(* Logix 5000 project; controller GracoPd2kDual_Example vendor 1 type 14 code 196 rev 32.11; software revision 32.04; part 3 of 4 *)

ADD_ON_INSTRUCTION GracoPd2kDual_SendDCS   (* revision 1.0 *)
// Help:
// Sends a dynamic command structure (DCS) to the PD2K system.
// For more information about DCS commands, see the system operation manual.
// State Codes:
// * 0000 (IDLE) - Idle
// * 1000 (BUSY) - Busy
// * 2000 (DONE) - Done
// * 4000 (ABORT) - Command overwritten by another process
// * 8000 (ERROR) - Invalid command ID
// * 8001 (ERROR) - Timeout waiting for DCS registers
// * 8002 (ERROR) - Command unsuccessful
VAR_IN_OUT
   io_moduleStatus : DINT[62]; {required}   // Data from device to PLC
   io_moduleCmds : DINT[30]; {required}   // Data from PLC to device
END_VAR
VAR_INPUT
   i_execute : BOOL; {visible}   // Execute command
   i_cmdID : DINT; {visible}   // Command ID number
   i_arg0 : DINT; {visible}   // Argument 0
   i_arg1 : DINT; {visible}   // Argument 1
   i_arg2 : DINT; {visible}   // Argument 2
   i_arg3 : DINT; {visible}   // Argument 3
   i_arg4 : DINT; {visible}   // Argument 4
   i_arg5 : DINT; {visible}   // Argument 5
   i_arg6 : DINT; {visible}   // Argument 6
   i_arg7 : DINT; {visible}   // Argument 7
   i_arg8 : DINT; {visible}   // Argument 8
END_VAR
VAR_OUTPUT
   o_return0 : DINT; {access Read Only, visible}   // Return 0
   o_return1 : DINT; {access Read Only, visible}   // Return 1
   o_return2 : DINT; {access Read Only, visible}   // Return 2
   o_return3 : DINT; {access Read Only, visible}   // Return 3
   o_return4 : DINT; {access Read Only, visible}   // Return 4
   o_return5 : DINT; {access Read Only, visible}   // Return 5
   o_return6 : DINT; {access Read Only, visible}   // Return 6
   o_return7 : DINT; {access Read Only, visible}   // Return 7
   o_return8 : DINT; {access Read Only, visible}   // Return 8
   o_done : BOOL; {access Read Only, visible}   // Done flag
   o_busy : BOOL; {access Read Only, visible}   // Busy flag
   o_aborted : BOOL; {access Read Only, visible}   // Aborted flag
   o_error : BOOL; {access Read Only, visible}   // Error flag
   o_state : DINT; {access Read Only, visible}   // Command state
END_VAR
VAR
   _resetArgsTmr : TIMER := (PRE := 100); {access None}   // Reset arguments delay timer
   _inUseTmr : TIMER := (PRE := 5000); {access None}   // Register in use timer
   _sendArgsTmr : TIMER := (PRE := 100); {access None}   // Send arguments timer
   rateLimitTmr : TIMER := (PRE := 250); {access None}   // Rate limit timer
   cmdTimeoutTmr : TIMER := (PRE := 5000); {access None}   // Command timeout timer
   state_checkDcsReg : DINT; {access None}
   state_clearArgs : DINT; {access None}
   state_setArgs : DINT; {access None}
   state_setCmdID : DINT; {access None}
   state_awaitAck : DINT; {access None}
   state_rateLimit : DINT; {access None}
   state_done : DINT; {access None}
   state_aborted : DINT; {access None}
   state_invalidCmdID : DINT; {access None}
   state_dcsRegInUse : DINT; {access None}
   state_ackError : DINT; {access None}
   state_ackTimeout : DINT; {access None}
   initConfigValsDone : BOOL; {access None}
   _nextState : DINT; {access None}
   dcsRegAvailable : BOOL; {access None}
   _cmdID : DINT; {access None}
   execute_ons : BOOL; {access None}
END_VAR

ROUTINE Logic   (* ladder *)
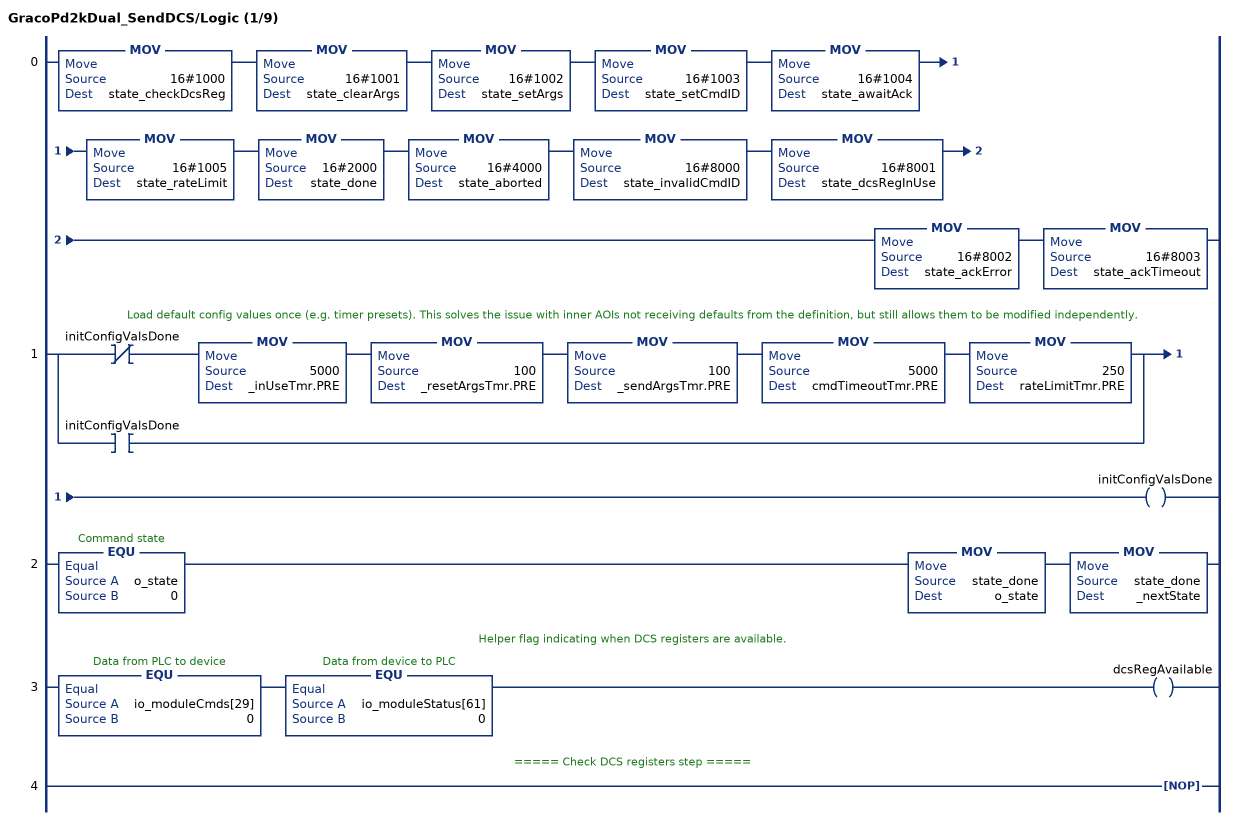
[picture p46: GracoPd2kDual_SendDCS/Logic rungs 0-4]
   0: MOV(16#1000,state_checkDcsReg)MOV(16#1001,state_clearArgs)MOV(16#1002,state_setArgs)MOV(16#1003,state_setCmdID)MOV(16#1004,state_awaitAck)MOV(16#1005,state_rateLimit)MOV(16#2000,state_done)MOV(16#4000,state_aborted)MOV(16#8000,state_invalidCmdID)MOV(16#8001,state_dcsRegInUse)MOV(16#8002,state_ackError)MOV(16#8003,state_ackTimeout);
   // Load default config values once (e.g. timer presets). This solves the issue with inner AOIs not receiving defaults from the definition, but still allows them to be modified independently.
   1: [XIO(initConfigValsDone) MOV(5000,_inUseTmr.PRE) MOV(100,_resetArgsTmr.PRE) MOV(100,_sendArgsTmr.PRE) MOV(5000,cmdTimeoutTmr.PRE) MOV(250,rateLimitTmr.PRE) ,XIC(initConfigValsDone) ]OTE(initConfigValsDone);
   2: EQU(o_state,0)MOV(state_done,o_state)MOV(state_done,_nextState);
   // Helper flag indicating when DCS registers are available.
   3: EQU(io_moduleCmds[29],0)EQU(io_moduleStatus[61],0)OTE(dcsRegAvailable);
   // ===== Check DCS registers step =====
   4: NOP();
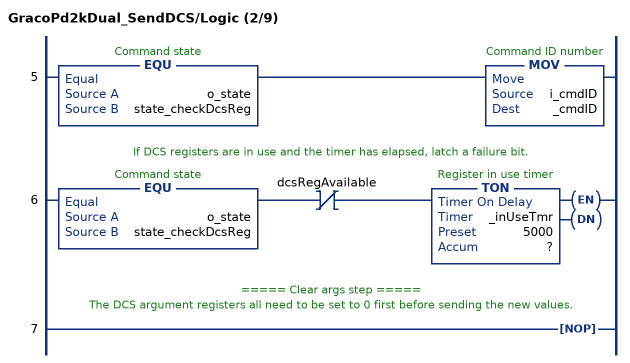
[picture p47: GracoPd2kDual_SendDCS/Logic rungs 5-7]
   5: EQU(o_state,state_checkDcsReg)MOV(i_cmdID,_cmdID);
   // If DCS registers are in use and the timer has elapsed, latch a failure bit.
   6: EQU(o_state,state_checkDcsReg)XIO(dcsRegAvailable)TON(_inUseTmr,?,?);
   // ===== Clear args step =====
   // The DCS argument registers all need to be set to 0 first before sending the new values.
   7: NOP();
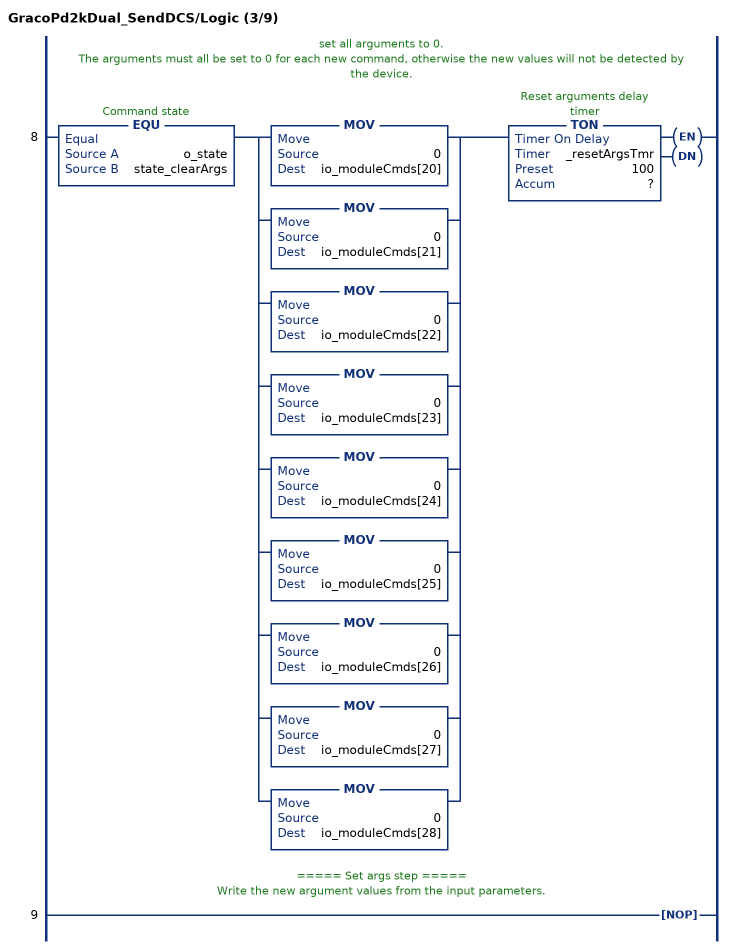
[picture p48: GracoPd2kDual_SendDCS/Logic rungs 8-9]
   // set all arguments to 0.
   // 		The arguments must all be set to 0 for each new command, otherwise the new values will not be detected by the device.
   8: EQU(o_state,state_clearArgs)[MOV(0,io_moduleCmds[20]) ,MOV(0,io_moduleCmds[21]) ,MOV(0,io_moduleCmds[22]) ,MOV(0,io_moduleCmds[23]) ,MOV(0,io_moduleCmds[24]) ,MOV(0,io_moduleCmds[25]) ,MOV(0,io_moduleCmds[26]) ,MOV(0,io_moduleCmds[27]) ,MOV(0,io_moduleCmds[28]) ]TON(_resetArgsTmr,?,?);
   // ===== Set args step =====
   // Write the new argument values from the input parameters.
   9: NOP();
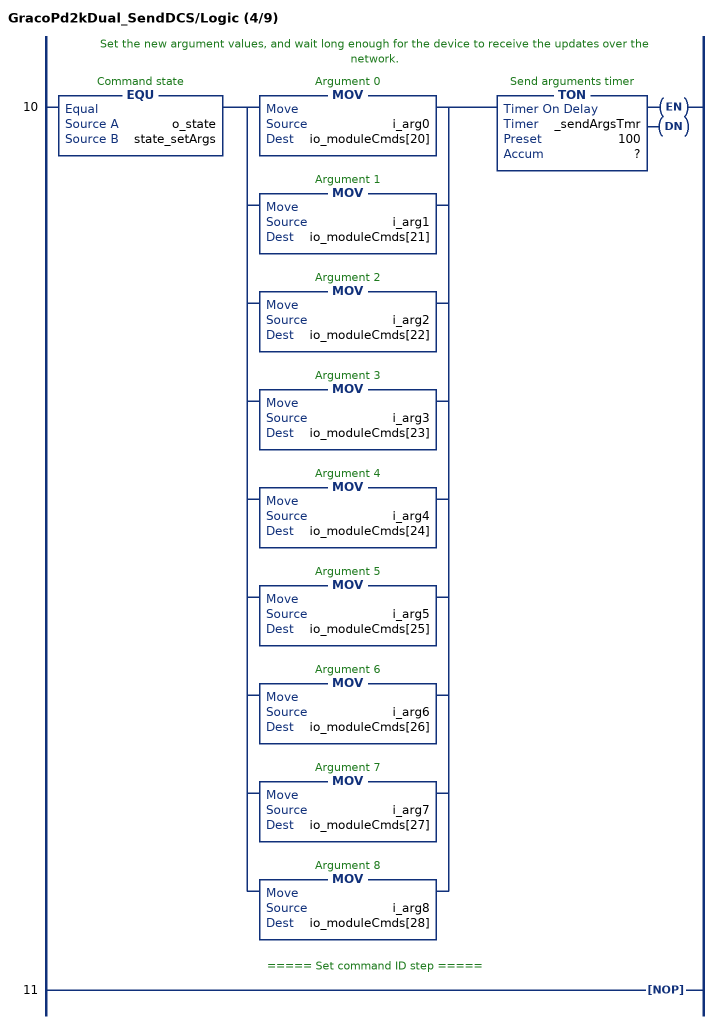
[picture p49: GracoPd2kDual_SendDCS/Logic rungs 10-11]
   // Set the new argument values, and wait long enough for the device to receive the updates over the network.
   10: EQU(o_state,state_setArgs)[MOV(i_arg0,io_moduleCmds[20]) ,MOV(i_arg1,io_moduleCmds[21]) ,MOV(i_arg2,io_moduleCmds[22]) ,MOV(i_arg3,io_moduleCmds[23]) ,MOV(i_arg4,io_moduleCmds[24]) ,MOV(i_arg5,io_moduleCmds[25]) ,MOV(i_arg6,io_moduleCmds[26]) ,MOV(i_arg7,io_moduleCmds[27]) ,MOV(i_arg8,io_moduleCmds[28]) ]TON(_sendArgsTmr,?,?);
   // ===== Set command ID step =====
   11: NOP();
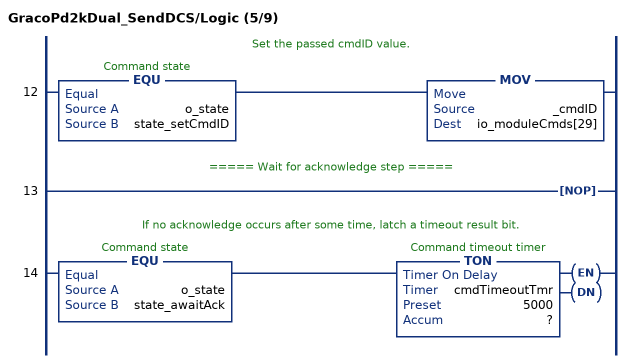
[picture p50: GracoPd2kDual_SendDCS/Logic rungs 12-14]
   // Set the passed cmdID value.
   12: EQU(o_state,state_setCmdID)MOV(_cmdID,io_moduleCmds[29]);
   // ===== Wait for acknowledge step =====
   13: NOP();
   // If no acknowledge occurs after some time, latch a timeout result bit.
   14: EQU(o_state,state_awaitAck)TON(cmdTimeoutTmr,?,?);
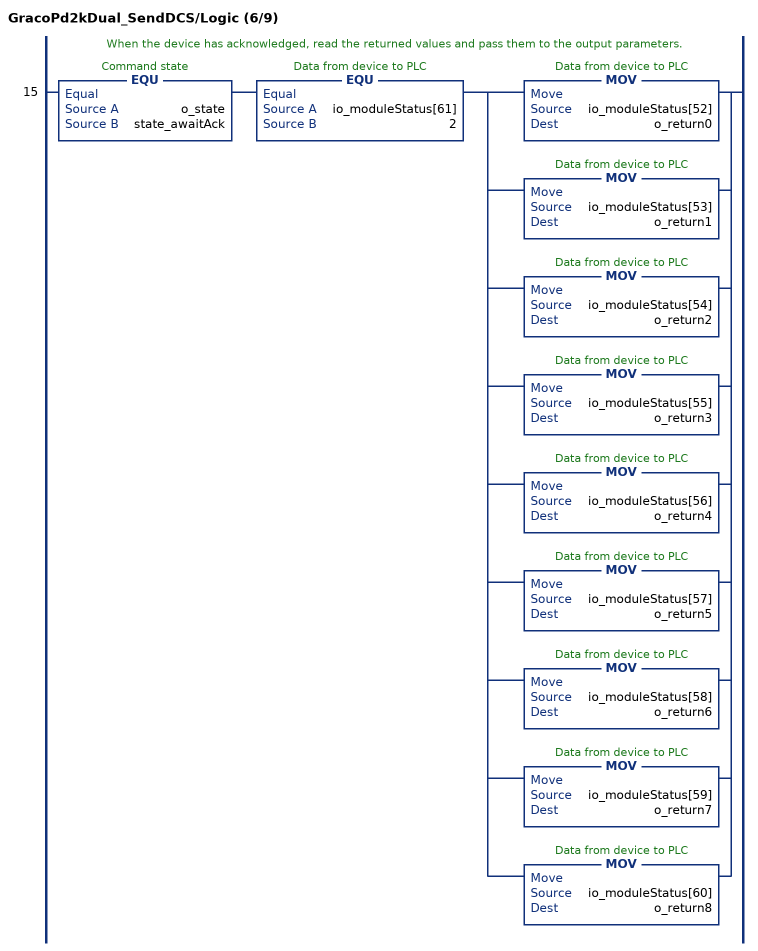
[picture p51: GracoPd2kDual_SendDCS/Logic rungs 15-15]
   // When the device has acknowledged, read the returned values and pass them to the output parameters.
   15: EQU(o_state,state_awaitAck)EQU(io_moduleStatus[61],2)[MOV(io_moduleStatus[52],o_return0) ,MOV(io_moduleStatus[53],o_return1) ,MOV(io_moduleStatus[54],o_return2) ,MOV(io_moduleStatus[55],o_return3) ,MOV(io_moduleStatus[56],o_return4) ,MOV(io_moduleStatus[57],o_return5) ,MOV(io_moduleStatus[58],o_return6) ,MOV(io_moduleStatus[59],o_return7) ,MOV(io_moduleStatus[60],o_return8) ];
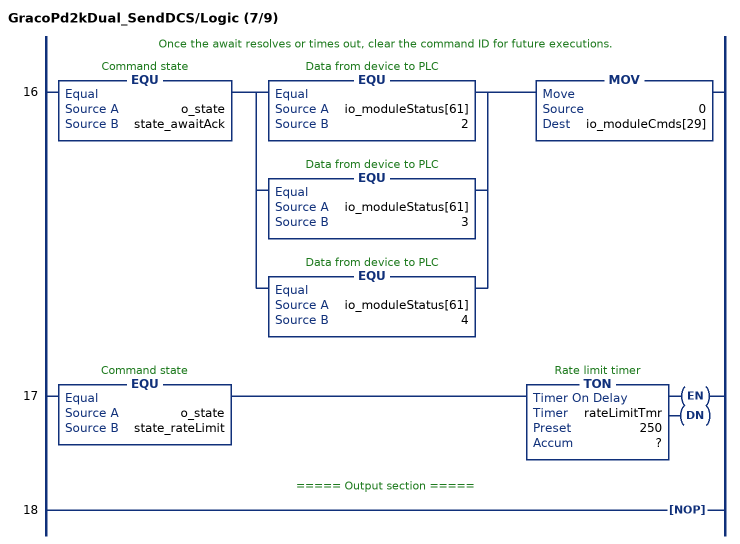
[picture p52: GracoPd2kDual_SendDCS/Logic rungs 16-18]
   // Once the await resolves or times out, clear the command ID for future executions.
   16: EQU(o_state,state_awaitAck)[EQU(io_moduleStatus[61],2) ,EQU(io_moduleStatus[61],3) ,EQU(io_moduleStatus[61],4) ]MOV(0,io_moduleCmds[29]);
   17: EQU(o_state,state_rateLimit)TON(rateLimitTmr,?,?);
   // ===== Output section =====
   18: NOP();
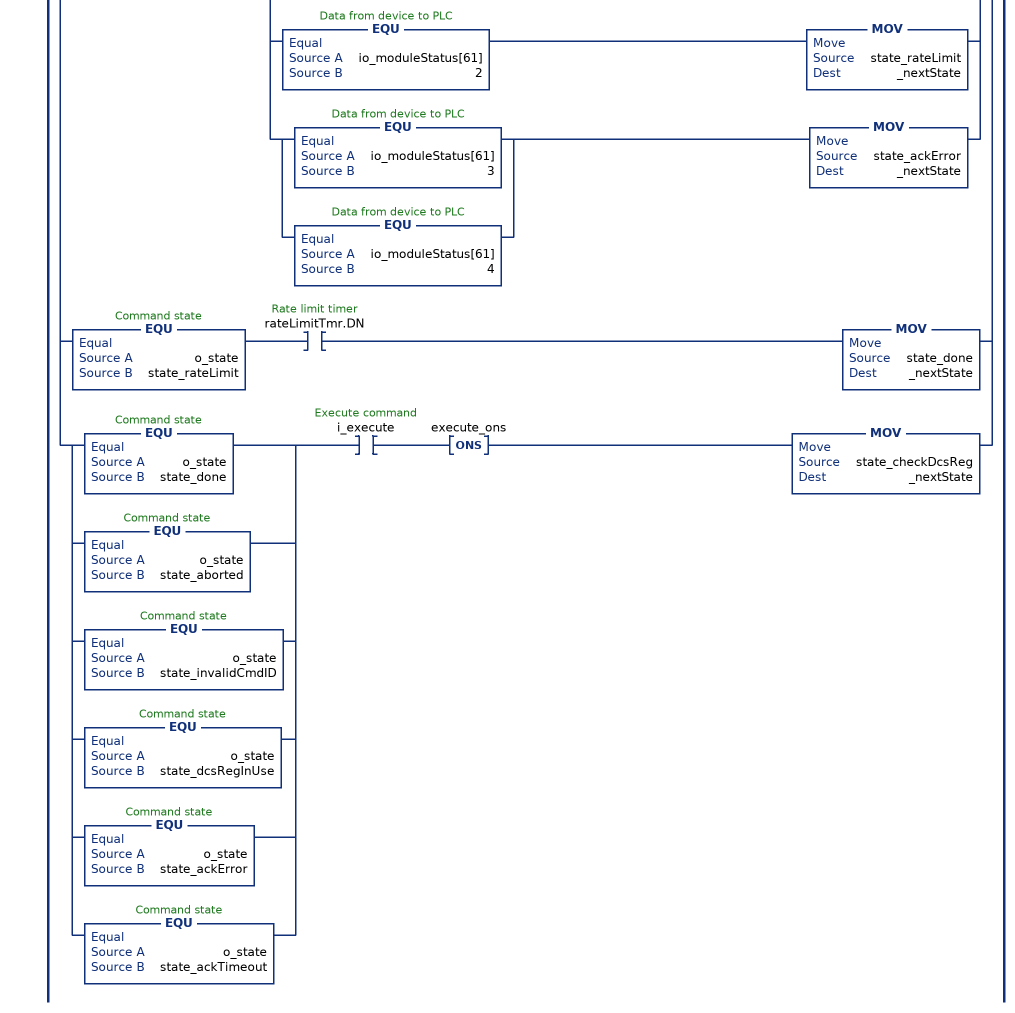
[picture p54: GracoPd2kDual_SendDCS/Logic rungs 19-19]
   19: [EQU(o_state,state_checkDcsReg) [EQU(_cmdID,0) MOV(state_invalidCmdID,_nextState) ,NEQ(_cmdID,0) [XIC(dcsRegAvailable) MOV(state_clearArgs,_nextState) ,XIC(_inUseTmr.DN) MOV(state_dcsRegInUse,_nextState) ] ] ,EQU(o_state,state_clearArgs) [XIO(dcsRegAvailable) MOV(state_checkDcsReg,_nextState) ,XIC(_resetArgsTmr.DN) MOV(state_setArgs,_nextState) ] ,EQU(o_state,state_setArgs) [XIO(dcsRegAvailable) MOV(state_checkDcsReg,_nextState) ,XIC(_sendArgsTmr.DN) MOV(state_setCmdID,_nextState) ] ,EQU(o_state,state_setCmdID) MOV(state_awaitAck,_nextState) ,EQU(o_state,state_awaitAck) [[EQU(io_moduleStatus[61],0) ,EQU(io_moduleStatus[61],1) ] [NEQ(io_moduleCmds[29],_cmdID) MOV(state_aborted,_nextState) ,XIC(cmdTimeoutTmr.DN) MOV(state_ackTimeout,_nextState) ] ,EQU(io_moduleStatus[61],2) MOV(state_rateLimit,_nextState) ,[EQU(io_moduleStatus[61],3) ,EQU(io_moduleStatus[61],4) ] MOV(state_ackError,_nextState) ] ,EQU(o_state,state_rateLimit) XIC(rateLimitTmr.DN) MOV(state_done,_nextState) ,[EQU(o_state,state_done) ,EQU(o_state,state_aborted) ,EQU(o_state,state_invalidCmdID) ,EQU(o_state,state_dcsRegInUse) ,EQU(o_state,state_ackError) ,EQU(o_state,state_ackTimeout) ] XIC(i_execute) ONS(execute_ons) MOV(state_checkDcsReg,_nextState) ];
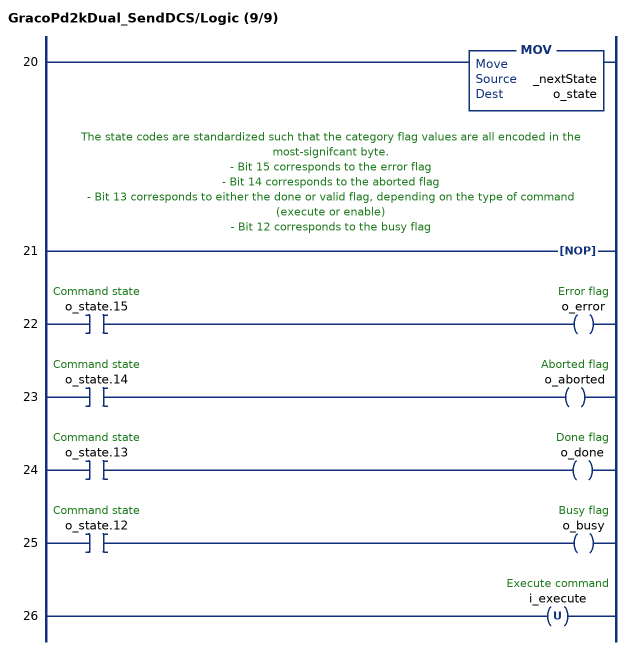
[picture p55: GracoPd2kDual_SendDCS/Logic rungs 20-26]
   20: MOV(_nextState,o_state);
   // The state codes are standardized such that the category flag values are all encoded in the most-signifcant byte.
   // - Bit 15 corresponds to the error flag
   // - Bit 14 corresponds to the aborted flag
   // - Bit 13 corresponds to either the done or valid flag, depending on the type of command (execute or enable)
   // - Bit 12 corresponds to the busy flag
   21: NOP();
   22: XIC(o_state.15)OTE(o_error);
   23: XIC(o_state.14)OTE(o_aborted);
   24: XIC(o_state.13)OTE(o_done);
   25: XIC(o_state.12)OTE(o_busy);
   26: OTU(i_execute);
END_ROUTINE
END_ADD_ON_INSTRUCTION

ADD_ON_INSTRUCTION GracoPd2kDual_StatusToUDT   (* revision 1.0 *)
// Help:
// Returns structured data from the module as a UDT.
VAR_IN_OUT
   io_moduleStatus : DINT[62]; {required}   // Data from device to PLC
   io_statusUDT : GracoPd2kDual_TypePd2kDualStatus; {required}   // Status UDT
END_VAR

ROUTINE Logic   (* ladder *)
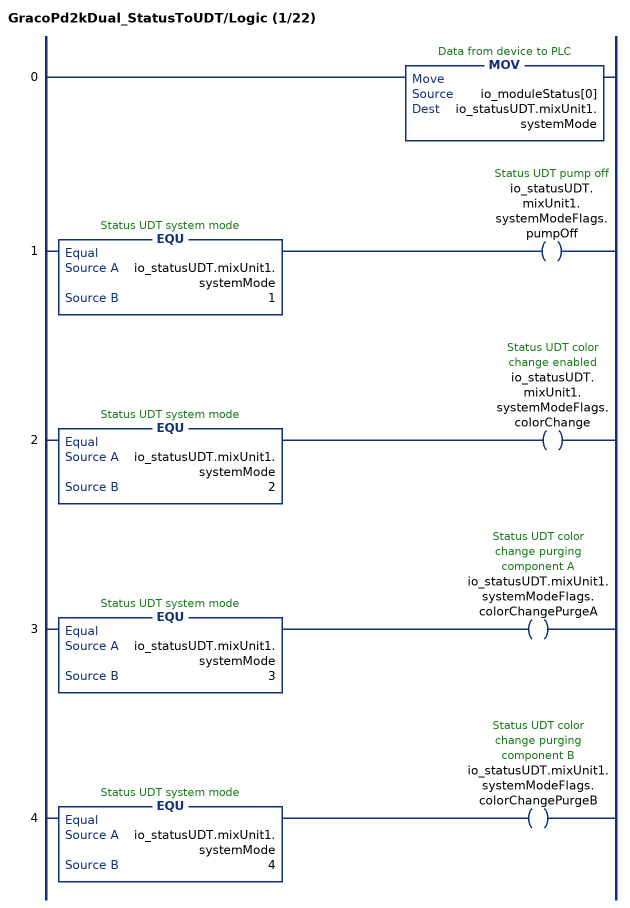
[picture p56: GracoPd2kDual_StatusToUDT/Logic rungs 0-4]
   0: MOV(io_moduleStatus[0],io_statusUDT.mixUnit1.systemMode);
   1: EQU(io_statusUDT.mixUnit1.systemMode,1)OTE(io_statusUDT.mixUnit1.systemModeFlags.pumpOff);
   2: EQU(io_statusUDT.mixUnit1.systemMode,2)OTE(io_statusUDT.mixUnit1.systemModeFlags.colorChange);
   3: EQU(io_statusUDT.mixUnit1.systemMode,3)OTE(io_statusUDT.mixUnit1.systemModeFlags.colorChangePurgeA);
   4: EQU(io_statusUDT.mixUnit1.systemMode,4)OTE(io_statusUDT.mixUnit1.systemModeFlags.colorChangePurgeB);
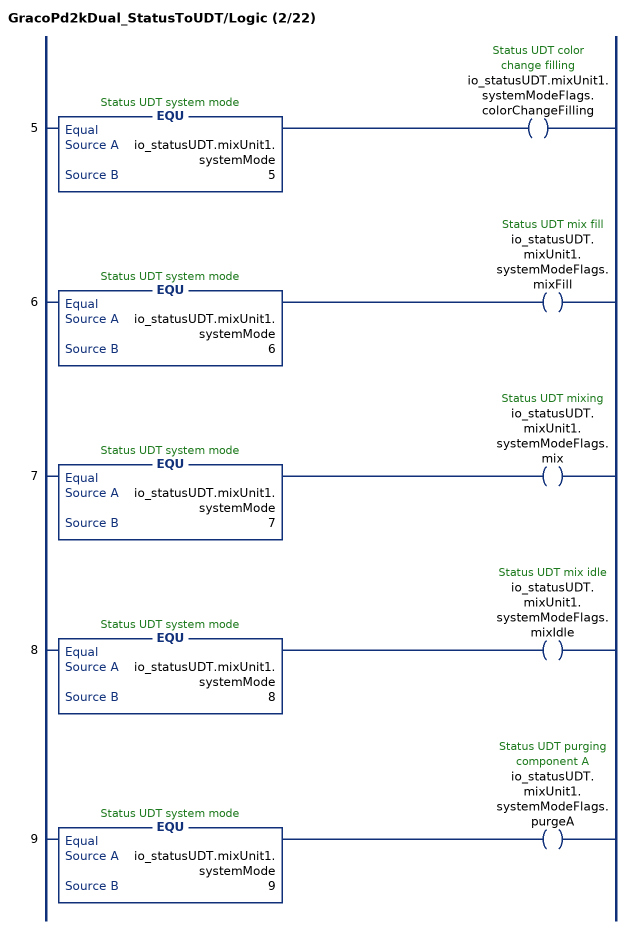
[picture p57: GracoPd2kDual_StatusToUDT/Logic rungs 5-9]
   5: EQU(io_statusUDT.mixUnit1.systemMode,5)OTE(io_statusUDT.mixUnit1.systemModeFlags.colorChangeFilling);
   6: EQU(io_statusUDT.mixUnit1.systemMode,6)OTE(io_statusUDT.mixUnit1.systemModeFlags.mixFill);
   7: EQU(io_statusUDT.mixUnit1.systemMode,7)OTE(io_statusUDT.mixUnit1.systemModeFlags.mix);
   8: EQU(io_statusUDT.mixUnit1.systemMode,8)OTE(io_statusUDT.mixUnit1.systemModeFlags.mixIdle);
   9: EQU(io_statusUDT.mixUnit1.systemMode,9)OTE(io_statusUDT.mixUnit1.systemModeFlags.purgeA);
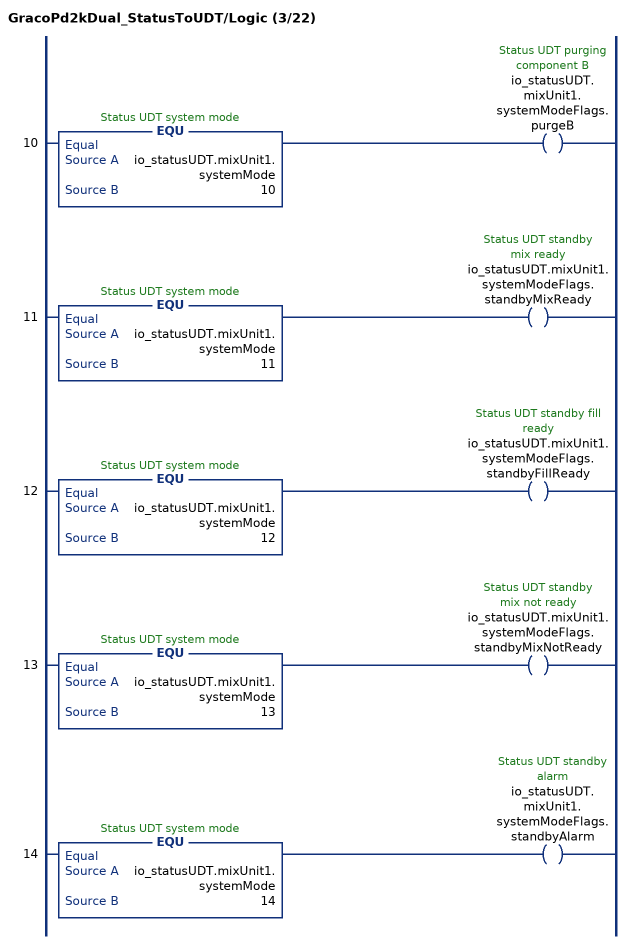
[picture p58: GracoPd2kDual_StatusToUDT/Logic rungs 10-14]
   10: EQU(io_statusUDT.mixUnit1.systemMode,10)OTE(io_statusUDT.mixUnit1.systemModeFlags.purgeB);
   11: EQU(io_statusUDT.mixUnit1.systemMode,11)OTE(io_statusUDT.mixUnit1.systemModeFlags.standbyMixReady);
   12: EQU(io_statusUDT.mixUnit1.systemMode,12)OTE(io_statusUDT.mixUnit1.systemModeFlags.standbyFillReady);
   13: EQU(io_statusUDT.mixUnit1.systemMode,13)OTE(io_statusUDT.mixUnit1.systemModeFlags.standbyMixNotReady);
   14: EQU(io_statusUDT.mixUnit1.systemMode,14)OTE(io_statusUDT.mixUnit1.systemModeFlags.standbyAlarm);
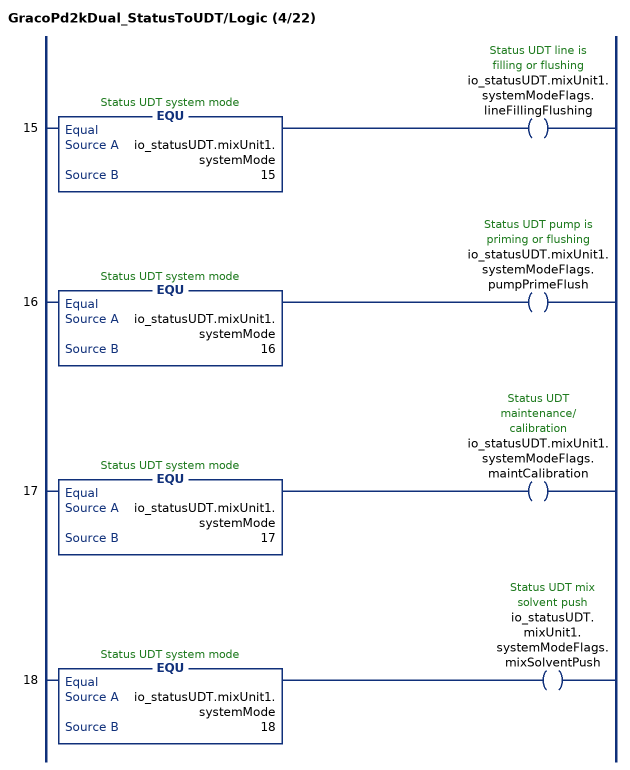
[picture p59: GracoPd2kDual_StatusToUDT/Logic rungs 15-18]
   15: EQU(io_statusUDT.mixUnit1.systemMode,15)OTE(io_statusUDT.mixUnit1.systemModeFlags.lineFillingFlushing);
   16: EQU(io_statusUDT.mixUnit1.systemMode,16)OTE(io_statusUDT.mixUnit1.systemModeFlags.pumpPrimeFlush);
   17: EQU(io_statusUDT.mixUnit1.systemMode,17)OTE(io_statusUDT.mixUnit1.systemModeFlags.maintCalibration);
   18: EQU(io_statusUDT.mixUnit1.systemMode,18)OTE(io_statusUDT.mixUnit1.systemModeFlags.mixSolventPush);
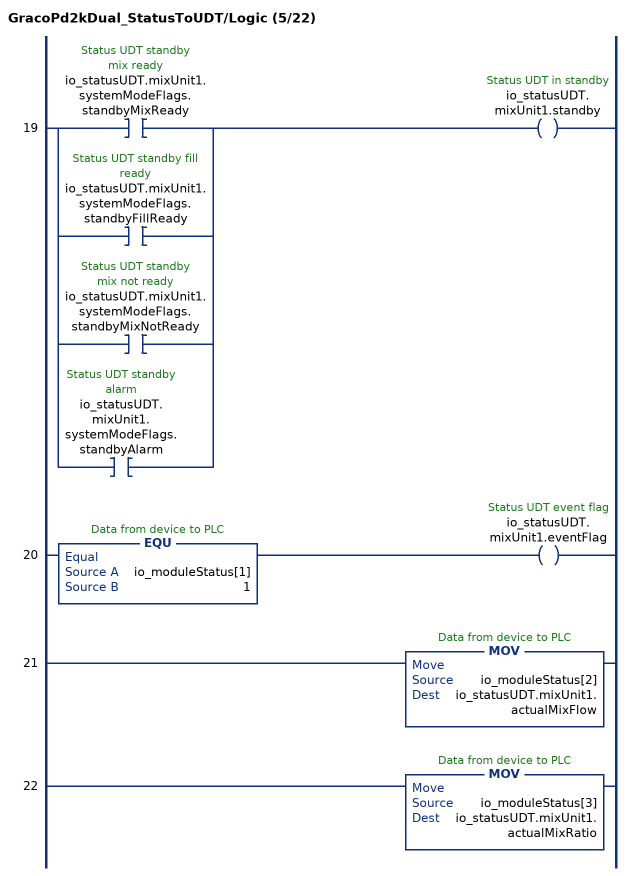
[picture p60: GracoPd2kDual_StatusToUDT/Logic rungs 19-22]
   19: [XIC(io_statusUDT.mixUnit1.systemModeFlags.standbyMixReady) ,XIC(io_statusUDT.mixUnit1.systemModeFlags.standbyFillReady) ,XIC(io_statusUDT.mixUnit1.systemModeFlags.standbyMixNotReady) ,XIC(io_statusUDT.mixUnit1.systemModeFlags.standbyAlarm) ]OTE(io_statusUDT.mixUnit1.standby);
   20: EQU(io_moduleStatus[1],1)OTE(io_statusUDT.mixUnit1.eventFlag);
   21: MOV(io_moduleStatus[2],io_statusUDT.mixUnit1.actualMixFlow);
   22: MOV(io_moduleStatus[3],io_statusUDT.mixUnit1.actualMixRatio);
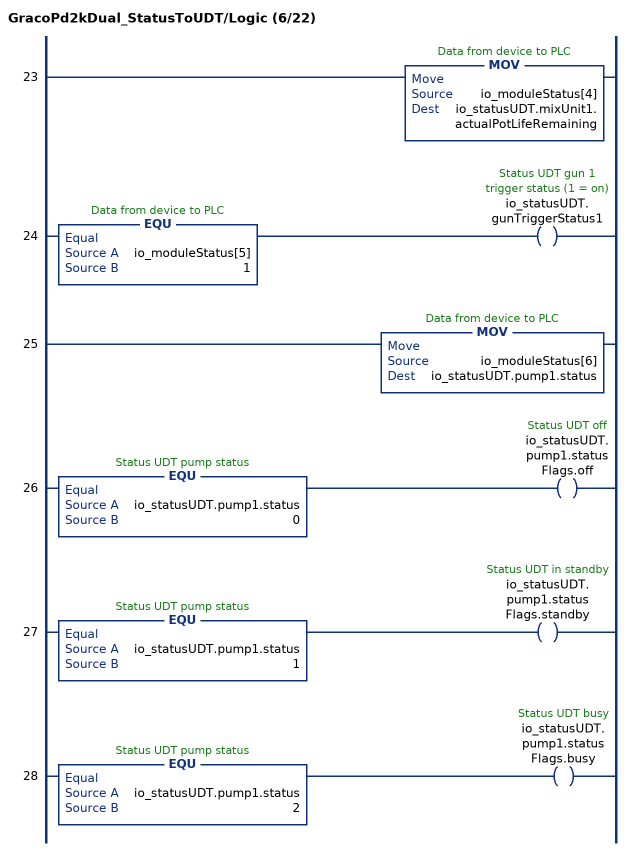
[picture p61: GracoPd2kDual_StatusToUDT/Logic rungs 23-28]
   23: MOV(io_moduleStatus[4],io_statusUDT.mixUnit1.actualPotLifeRemaining);
   24: EQU(io_moduleStatus[5],1)OTE(io_statusUDT.gunTriggerStatus1);
   25: MOV(io_moduleStatus[6],io_statusUDT.pump1.status);
   26: EQU(io_statusUDT.pump1.status,0)OTE(io_statusUDT.pump1.statusFlags.off);
   27: EQU(io_statusUDT.pump1.status,1)OTE(io_statusUDT.pump1.statusFlags.standby);
   28: EQU(io_statusUDT.pump1.status,2)OTE(io_statusUDT.pump1.statusFlags.busy);
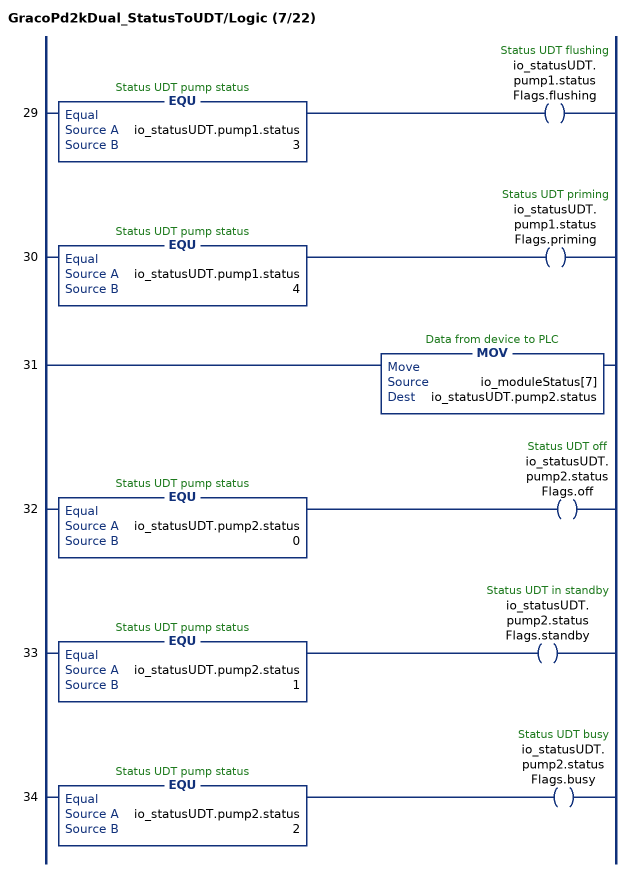
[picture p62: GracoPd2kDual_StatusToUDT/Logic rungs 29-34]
   29: EQU(io_statusUDT.pump1.status,3)OTE(io_statusUDT.pump1.statusFlags.flushing);
   30: EQU(io_statusUDT.pump1.status,4)OTE(io_statusUDT.pump1.statusFlags.priming);
   31: MOV(io_moduleStatus[7],io_statusUDT.pump2.status);
   32: EQU(io_statusUDT.pump2.status,0)OTE(io_statusUDT.pump2.statusFlags.off);
   33: EQU(io_statusUDT.pump2.status,1)OTE(io_statusUDT.pump2.statusFlags.standby);
   34: EQU(io_statusUDT.pump2.status,2)OTE(io_statusUDT.pump2.statusFlags.busy);
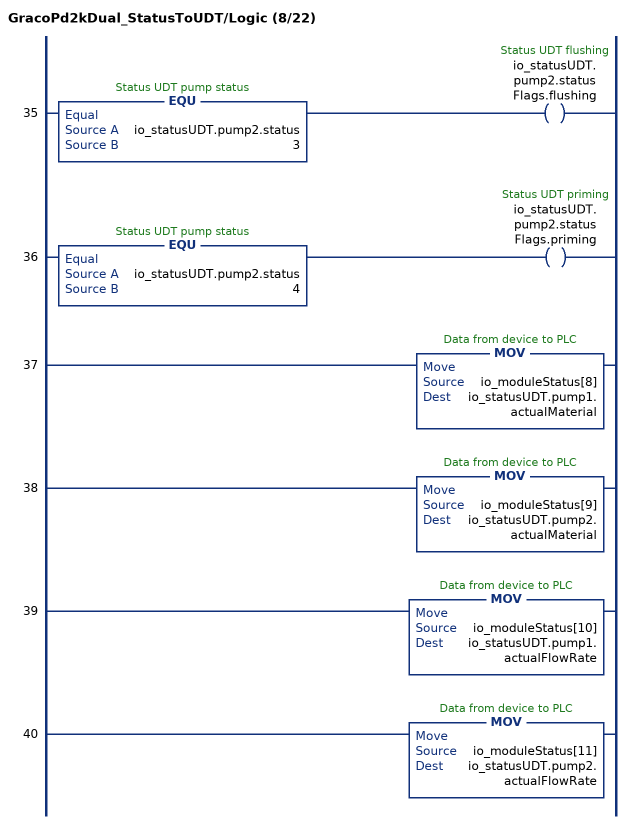
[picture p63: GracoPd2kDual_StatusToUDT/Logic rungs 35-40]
   35: EQU(io_statusUDT.pump2.status,3)OTE(io_statusUDT.pump2.statusFlags.flushing);
   36: EQU(io_statusUDT.pump2.status,4)OTE(io_statusUDT.pump2.statusFlags.priming);
   37: MOV(io_moduleStatus[8],io_statusUDT.pump1.actualMaterial);
   38: MOV(io_moduleStatus[9],io_statusUDT.pump2.actualMaterial);
   39: MOV(io_moduleStatus[10],io_statusUDT.pump1.actualFlowRate);
   40: MOV(io_moduleStatus[11],io_statusUDT.pump2.actualFlowRate);
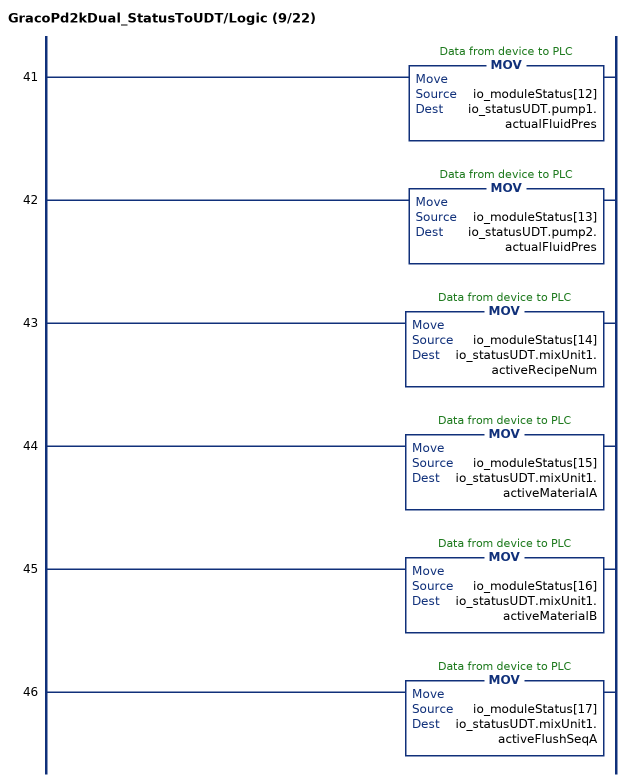
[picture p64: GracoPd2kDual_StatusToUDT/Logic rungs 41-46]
   41: MOV(io_moduleStatus[12],io_statusUDT.pump1.actualFluidPres);
   42: MOV(io_moduleStatus[13],io_statusUDT.pump2.actualFluidPres);
   43: MOV(io_moduleStatus[14],io_statusUDT.mixUnit1.activeRecipeNum);
   44: MOV(io_moduleStatus[15],io_statusUDT.mixUnit1.activeMaterialA);
   45: MOV(io_moduleStatus[16],io_statusUDT.mixUnit1.activeMaterialB);
   46: MOV(io_moduleStatus[17],io_statusUDT.mixUnit1.activeFlushSeqA);
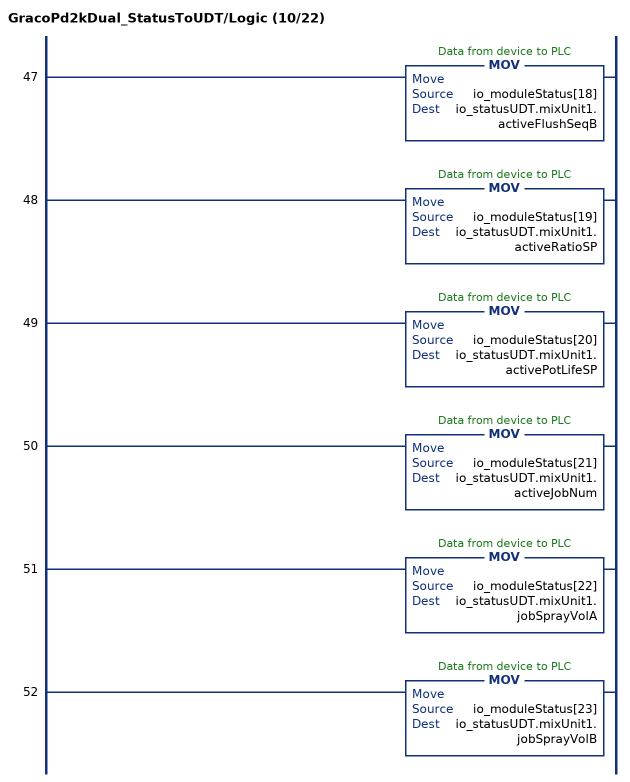
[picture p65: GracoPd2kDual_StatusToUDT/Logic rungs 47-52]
   47: MOV(io_moduleStatus[18],io_statusUDT.mixUnit1.activeFlushSeqB);
   48: MOV(io_moduleStatus[19],io_statusUDT.mixUnit1.activeRatioSP);
   49: MOV(io_moduleStatus[20],io_statusUDT.mixUnit1.activePotLifeSP);
   50: MOV(io_moduleStatus[21],io_statusUDT.mixUnit1.activeJobNum);
   51: MOV(io_moduleStatus[22],io_statusUDT.mixUnit1.jobSprayVolA);
   52: MOV(io_moduleStatus[23],io_statusUDT.mixUnit1.jobSprayVolB);
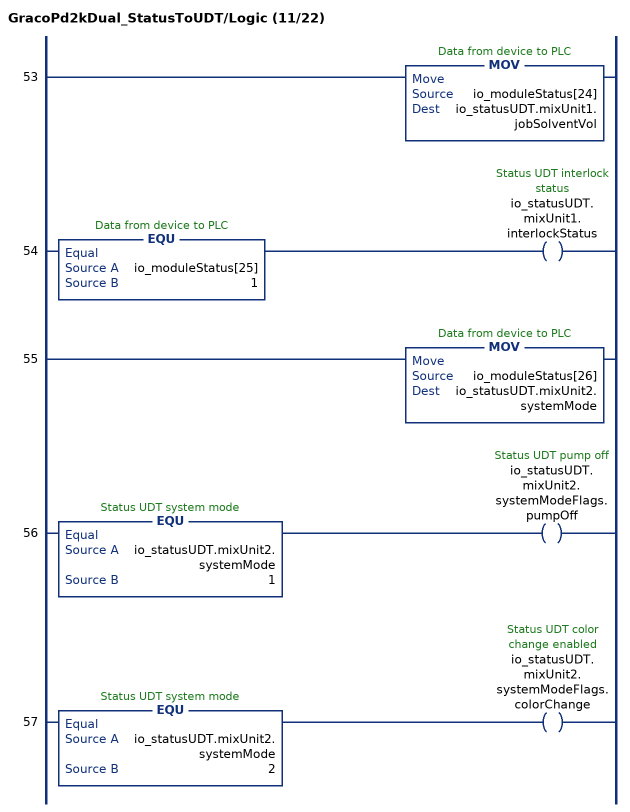
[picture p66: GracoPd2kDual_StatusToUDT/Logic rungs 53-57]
   53: MOV(io_moduleStatus[24],io_statusUDT.mixUnit1.jobSolventVol);
   54: EQU(io_moduleStatus[25],1)OTE(io_statusUDT.mixUnit1.interlockStatus);
   55: MOV(io_moduleStatus[26],io_statusUDT.mixUnit2.systemMode);
   56: EQU(io_statusUDT.mixUnit2.systemMode,1)OTE(io_statusUDT.mixUnit2.systemModeFlags.pumpOff);
   57: EQU(io_statusUDT.mixUnit2.systemMode,2)OTE(io_statusUDT.mixUnit2.systemModeFlags.colorChange);
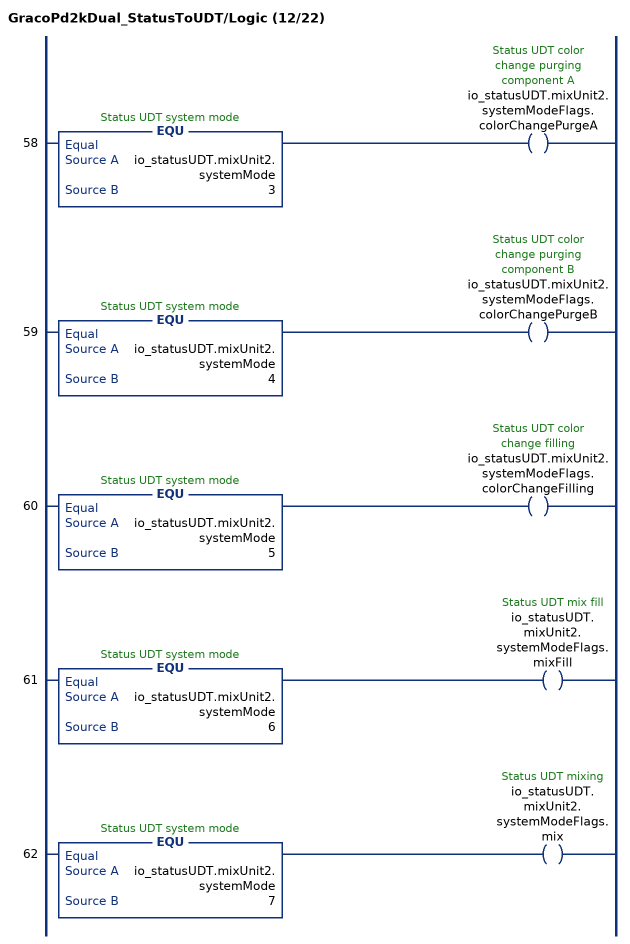
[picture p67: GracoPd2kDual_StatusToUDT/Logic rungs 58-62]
   58: EQU(io_statusUDT.mixUnit2.systemMode,3)OTE(io_statusUDT.mixUnit2.systemModeFlags.colorChangePurgeA);
   59: EQU(io_statusUDT.mixUnit2.systemMode,4)OTE(io_statusUDT.mixUnit2.systemModeFlags.colorChangePurgeB);
   60: EQU(io_statusUDT.mixUnit2.systemMode,5)OTE(io_statusUDT.mixUnit2.systemModeFlags.colorChangeFilling);
   61: EQU(io_statusUDT.mixUnit2.systemMode,6)OTE(io_statusUDT.mixUnit2.systemModeFlags.mixFill);
   62: EQU(io_statusUDT.mixUnit2.systemMode,7)OTE(io_statusUDT.mixUnit2.systemModeFlags.mix);
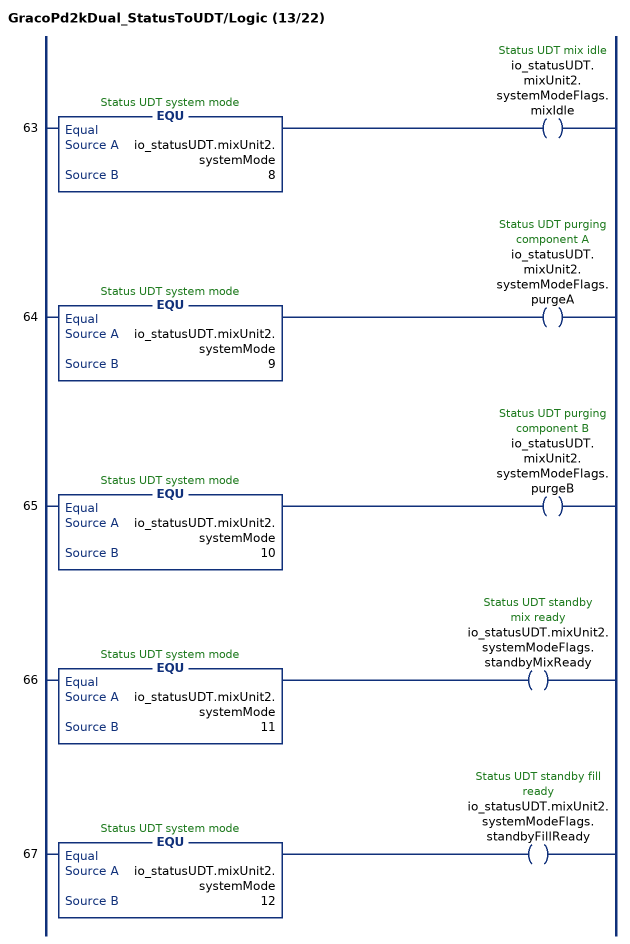
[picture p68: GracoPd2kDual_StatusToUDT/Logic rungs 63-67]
   63: EQU(io_statusUDT.mixUnit2.systemMode,8)OTE(io_statusUDT.mixUnit2.systemModeFlags.mixIdle);
   64: EQU(io_statusUDT.mixUnit2.systemMode,9)OTE(io_statusUDT.mixUnit2.systemModeFlags.purgeA);
   65: EQU(io_statusUDT.mixUnit2.systemMode,10)OTE(io_statusUDT.mixUnit2.systemModeFlags.purgeB);
   66: EQU(io_statusUDT.mixUnit2.systemMode,11)OTE(io_statusUDT.mixUnit2.systemModeFlags.standbyMixReady);
   67: EQU(io_statusUDT.mixUnit2.systemMode,12)OTE(io_statusUDT.mixUnit2.systemModeFlags.standbyFillReady);
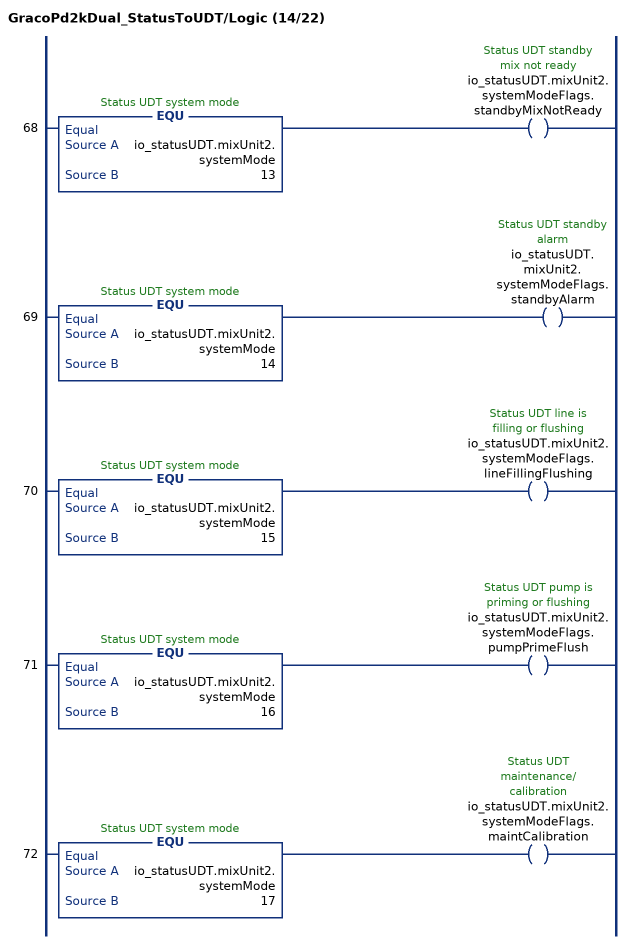
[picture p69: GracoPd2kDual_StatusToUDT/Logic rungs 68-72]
   68: EQU(io_statusUDT.mixUnit2.systemMode,13)OTE(io_statusUDT.mixUnit2.systemModeFlags.standbyMixNotReady);
   69: EQU(io_statusUDT.mixUnit2.systemMode,14)OTE(io_statusUDT.mixUnit2.systemModeFlags.standbyAlarm);
   70: EQU(io_statusUDT.mixUnit2.systemMode,15)OTE(io_statusUDT.mixUnit2.systemModeFlags.lineFillingFlushing);
   71: EQU(io_statusUDT.mixUnit2.systemMode,16)OTE(io_statusUDT.mixUnit2.systemModeFlags.pumpPrimeFlush);
   72: EQU(io_statusUDT.mixUnit2.systemMode,17)OTE(io_statusUDT.mixUnit2.systemModeFlags.maintCalibration);
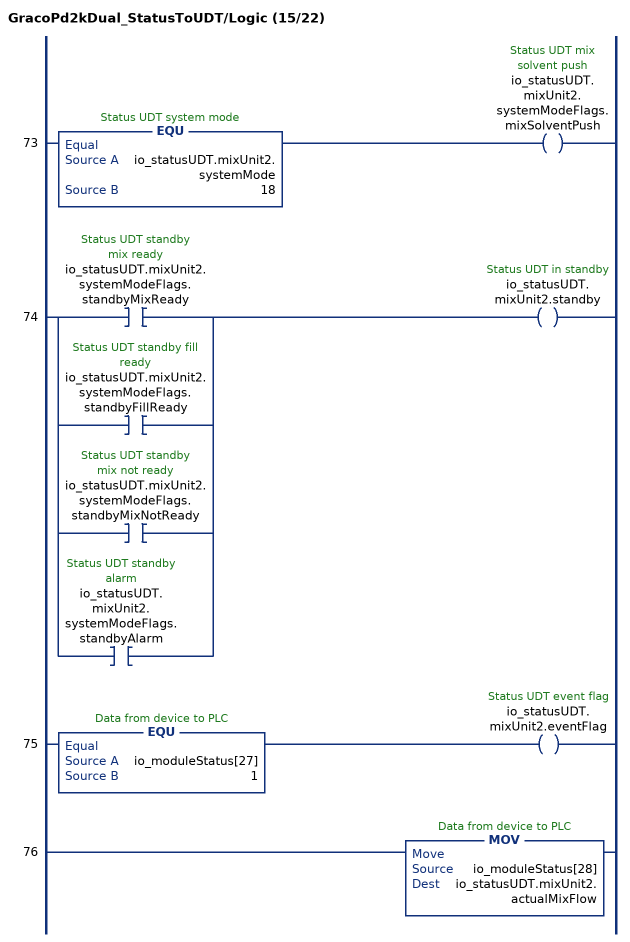
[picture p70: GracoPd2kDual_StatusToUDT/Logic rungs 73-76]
   73: EQU(io_statusUDT.mixUnit2.systemMode,18)OTE(io_statusUDT.mixUnit2.systemModeFlags.mixSolventPush);
   74: [XIC(io_statusUDT.mixUnit2.systemModeFlags.standbyMixReady) ,XIC(io_statusUDT.mixUnit2.systemModeFlags.standbyFillReady) ,XIC(io_statusUDT.mixUnit2.systemModeFlags.standbyMixNotReady) ,XIC(io_statusUDT.mixUnit2.systemModeFlags.standbyAlarm) ]OTE(io_statusUDT.mixUnit2.standby);
   75: EQU(io_moduleStatus[27],1)OTE(io_statusUDT.mixUnit2.eventFlag);
   76: MOV(io_moduleStatus[28],io_statusUDT.mixUnit2.actualMixFlow);
